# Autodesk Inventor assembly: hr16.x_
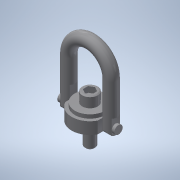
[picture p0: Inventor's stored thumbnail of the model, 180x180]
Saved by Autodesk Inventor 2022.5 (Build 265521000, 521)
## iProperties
Part Number: hr16.x_
Material: 一般
Document SubType Name: Assembly
Designer: ImaoCorp
Sending System: SOLIDWORKS 2017-2017317
MC: AMD64
MC_MODEL: Intel64 Family 6 Model 60 Stepping 3, GenuineIntel
OS: Windows_NT
FRU: Parasolid Version 29.0, build 201,  4-17-2017
FORMAT: text
GUISE: transmit
KEY: hr16
FILE: hr16.x_t
DATE: Mon Jul 01 17:37:27 2019
Author: ImaoCorp
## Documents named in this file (3)
- X:\14_SW2022-Inv2022\00_全2023-1023新製品(TCC)まで\h\hr16\HR16.iam
- X:\14_SW2022-Inv2022\00_全2023-1023新製品(TCC)まで\h\hr16\hr16_01.ipt
- X:\14_SW2022-Inv2022\00_全2023-1023新製品(TCC)まで\h\hr16\hr16_02.ipt
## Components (2 placed, 2 different names)
1. hr16_01
2. hr16_02
